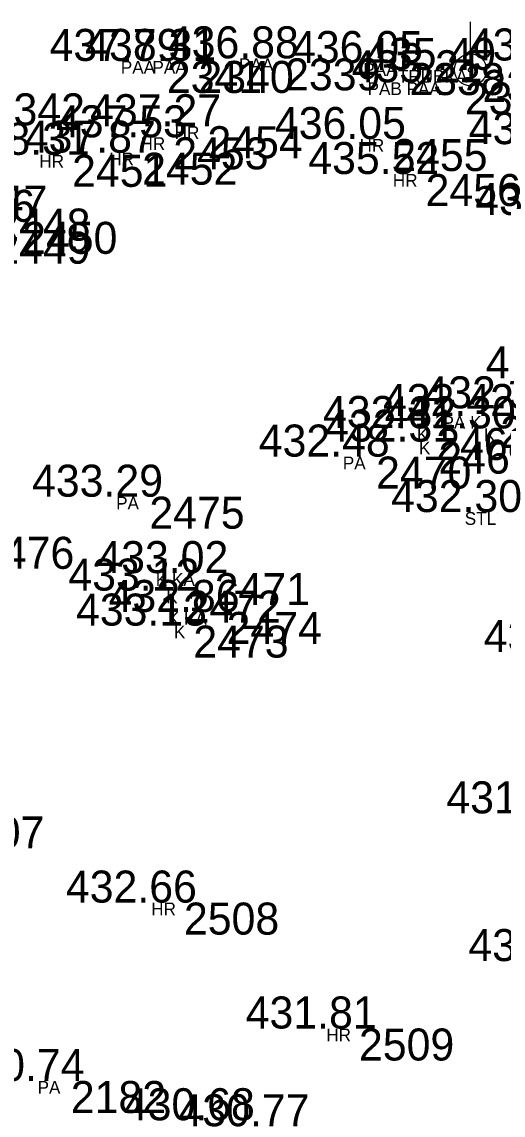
# Model space of a CAD drawing. Extents: x -639390 to -639075, y -1138747 to -1138358.
# Drawn here: x -639296.34 to -639285.06, y -1138588.15 to -1138562.53 of the extents above; entities that cross this region are included whole.
import ezdxf

# ---------------------------------------------------------------- set-up
doc = ezdxf.new("R2010")
doc.units = 0
for name, color, linetype in [('Vrstva 11', 7, 'Continuous'), ('Vrstva 12', 7, 'Continuous'), ('Vrstva 13', 7, 'Continuous'), ('Vrstva 21', 7, 'Continuous'), ('Vrstva 57', 7, 'Continuous')]:
    doc.layers.add(name, color=color, linetype=linetype)

msp = doc.modelspace()

# ---------------------------------------------------------------- linework, layer by layer
at = {"layer": 'Vrstva 11'}
for p, q in [((-639290.45, -1138563.39), (-639290.45, -1138563.39)), ((-639293.22, -1138563.45), (-639293.22, -1138563.45)), ((-639292.48, -1138563.45), (-639292.48, -1138563.45)), ((-639287.54, -1138563.5), (-639287.54, -1138563.5)), ((-639285.83, -1138563.66), (-639285.83, -1138563.66)), ((-639286.24, -1138563.95), (-639286.24, -1138563.95)), ((-639292.27, -1138564.98), (-639292.27, -1138564.98)), ((-639293.07, -1138565.24), (-639293.07, -1138565.24)), ((-639287.94, -1138565.28), (-639287.94, -1138565.28)), ((-639295.44, -1138565.65), (-639295.44, -1138565.65)), ((-639293.8, -1138565.6), (-639293.8, -1138565.6)), ((-639287.16, -1138566.1), (-639287.16, -1138566.1)), ((-639285.41, -1138571.77), (-639285.41, -1138571.77)), ((-639286.91, -1138572.05), (-639286.91, -1138572.05)), ((-639285.34, -1138572.06), (-639285.34, -1138572.06)), ((-639286.86, -1138572.37), (-639286.86, -1138572.37)), ((-639288.32, -1138572.72), (-639288.32, -1138572.72)), ((-639293.63, -1138573.66), (-639293.63, -1138573.66)), ((-639285.19, -1138574.02), (-639285.19, -1138574.02)), ((-639292.1, -1138575.45), (-639292.1, -1138575.45)), ((-639292.78, -1138575.86), (-639292.78, -1138575.86)), ((-639291.82, -1138576.36), (-639291.82, -1138576.36)), ((-639292.6, -1138576.68), (-639292.6, -1138576.68)), ((-639292.82, -1138583.17), (-639292.82, -1138583.17)), ((-639288.72, -1138586.12), (-639288.72, -1138586.12)), ((-639295.47, -1138587.35), (-639295.47, -1138587.35))]:
    msp.add_line(p, q, dxfattribs=at)
at = {"layer": 'Vrstva 21'}
msp.add_line((-639285.83, -1138563.285), (-639285.83, -1138562.535), dxfattribs=at)
for radius in [0.375, 0.05]:
    msp.add_circle((-639285.83, -1138563.66), radius, dxfattribs=at)

# ---------------------------------------------------------------- texts
at = {"layer": 'Vrstva 12'}
for s, p in [('437.89 ', (-639295.689, -1138563.45)), ('437.31 ', (-639294.855, -1138563.45)), ('436.88 ', (-639292.919, -1138563.39)), ('436.05 ', (-639290.01, -1138563.5)), ('435.22 ', (-639285.869, -1138563.44)), ('435.49 ', (-639288.299, -1138563.66)), ('435.21 ', (-639288.615, -1138563.95)), ('437.27 ', (-639294.739, -1138564.98)), ('437.53 ', (-639295.539, -1138565.24)), ('436.05 ', (-639290.41, -1138565.28)), ('434.30 ', (-639285.869, -1138565.4)), ('438.31 ', (-639297.815, -1138565.65)), ('437.87 ', (-639296.269, -1138565.6)), ('435.52 ', (-639289.629, -1138566.1)), ('438.26 ', (-639299.096, -1138567.22)), ('434.19 ', (-639285.719, -1138567.06)), ('432.45 ', (-639285.47, -1138570.89)), ('432.42 ', (-639287.879, -1138571.77)), ('432.37 ', (-639286.909, -1138571.59)), ('432.41 ', (-639289.285, -1138572.05)), ('432.30 ', (-639287.839, -1138572.06)), ('432.31 ', (-639289.235, -1138572.37)), ('432.48 ', (-639290.789, -1138572.72)), ('433.29 ', (-639296.099, -1138573.66)), ('432.30 ', (-639287.689, -1138574.02)), ('433.02 ', (-639294.569, -1138575.45)), ('433.12 ', (-639295.249, -1138575.86)), ('432.86 ', (-639294.306, -1138576.36)), ('433.13 ', (-639295.069, -1138576.68)), ('431.88 ', (-639285.519, -1138577.3)), ('431.61 ', (-639286.395, -1138581.08)), ('432.66 ', (-639295.306, -1138583.17)), ('431.20 ', (-639285.879, -1138584.54)), ('431.81 ', (-639291.095, -1138586.12)), ('430.74 ', (-639297.939, -1138587.35)), ('430.68 ', (-639293.949, -1138588.27)), ('430.77 ', (-639292.669, -1138588.41))]:
    msp.add_text(s, height=0.75, dxfattribs=at).set_placement(p)
at = {"layer": 'Vrstva 13'}
for s, p in [(' 2339', (-639290.45, -1138564.14)), (' 2341', (-639293.22, -1138564.2)), (' 2340', (-639292.48, -1138564.2)), (' 2338', (-639287.54, -1138564.25)), (' 2337', (-639285.83, -1138564.41)), (' 2336', (-639286.24, -1138564.7)), (' 2342', (-639297.37, -1138564.96)), (' 2454', (-639292.27, -1138565.73)), (' 2453', (-639293.07, -1138565.99)), (' 2455', (-639287.94, -1138566.03)), (' 2451', (-639295.44, -1138566.4)), (' 2452', (-639293.8, -1138566.35)), (' 2456', (-639287.16, -1138566.85)), (' 2447', (-639298.25, -1138567.12)), (' 2448', (-639297.24, -1138567.66)), (' 2450', (-639296.61, -1138567.97)), (' 2449', (-639297.24, -1138568.2)), (' 2465', (-639285.41, -1138572.52)), (' 2468', (-639286.91, -1138572.8)), (' 2467', (-639286.86, -1138573.12)), (' 2470', (-639288.32, -1138573.47)), (' 2475', (-639293.63, -1138574.41)), (' 2476', (-639297.62, -1138575.35)), (' 2471', (-639292.1, -1138576.2)), (' 2472', (-639292.78, -1138576.61)), (' 2474', (-639291.82, -1138577.11)), (' 2473', (-639292.6, -1138577.43)), (' 2507', (-639298.32, -1138581.9)), (' 2508', (-639292.82, -1138583.92)), (' 2509', (-639288.72, -1138586.87)), (' 2182', (-639295.47, -1138588.1))]:
    msp.add_text(s, height=0.75, dxfattribs=at).set_placement(p)
at = {"layer": 'Vrstva 57'}
for s, p in [('PAA', (-639291.25, -1138563.69)), ('PAA', (-639294.02, -1138563.75)), ('PAA', (-639293.28, -1138563.75)), ('PAA', (-639288.34, -1138563.8)), ('TRUBKA', (-639287.53, -1138563.96)), ('PAB PAA', (-639288.24, -1138564.25)), ('HR', (-639292.759, -1138565.28)), ('HR', (-639293.559, -1138565.54)), ('HR', (-639288.429, -1138565.58)), ('HR', (-639295.929, -1138565.95)), ('HR', (-639294.289, -1138565.9)), ('HR', (-639287.649, -1138566.4)), ('PA K', (-639286.485, -1138572.07)), ('K', (-639287.085, -1138572.35)), ('K', (-639285.515, -1138572.36)), ('K', (-639287.035, -1138572.67)), ('PA', (-639288.82, -1138573.02)), ('PA', (-639294.13, -1138573.96)), ('STL', (-639285.965, -1138574.32)), ('K KA', (-639293.2, -1138575.75)), ('K', (-639292.955, -1138576.16)), ('K KA', (-639292.92, -1138576.66)), ('K', (-639292.775, -1138576.98)), ('HR', (-639293.309, -1138583.47)), ('HR', (-639289.209, -1138586.42)), ('PA', (-639295.97, -1138587.65))]:
    msp.add_text(s, height=0.3, dxfattribs=at).set_placement(p)

doc.saveas('drawing.dxf')
